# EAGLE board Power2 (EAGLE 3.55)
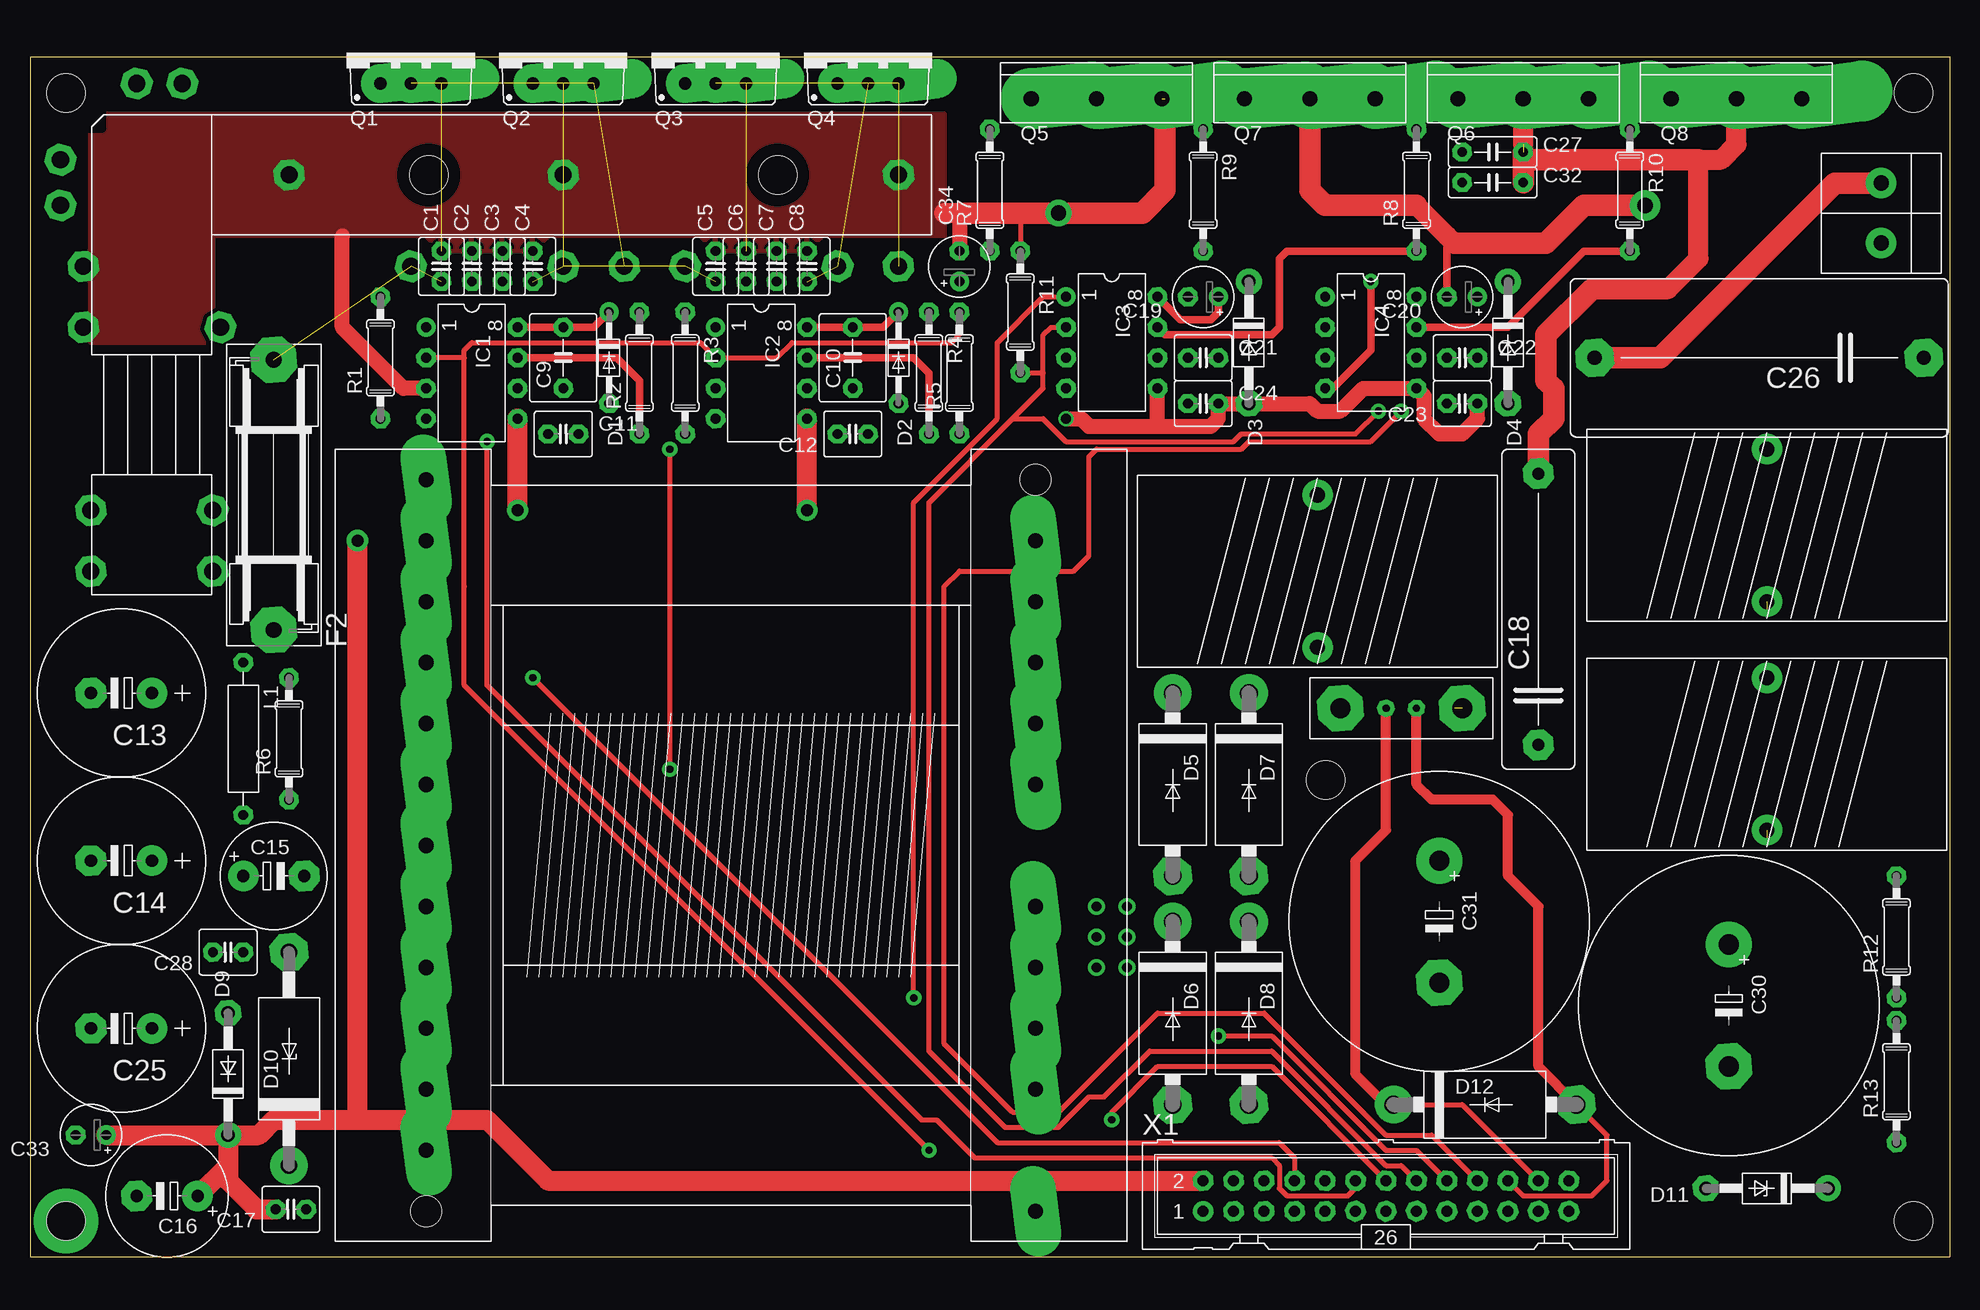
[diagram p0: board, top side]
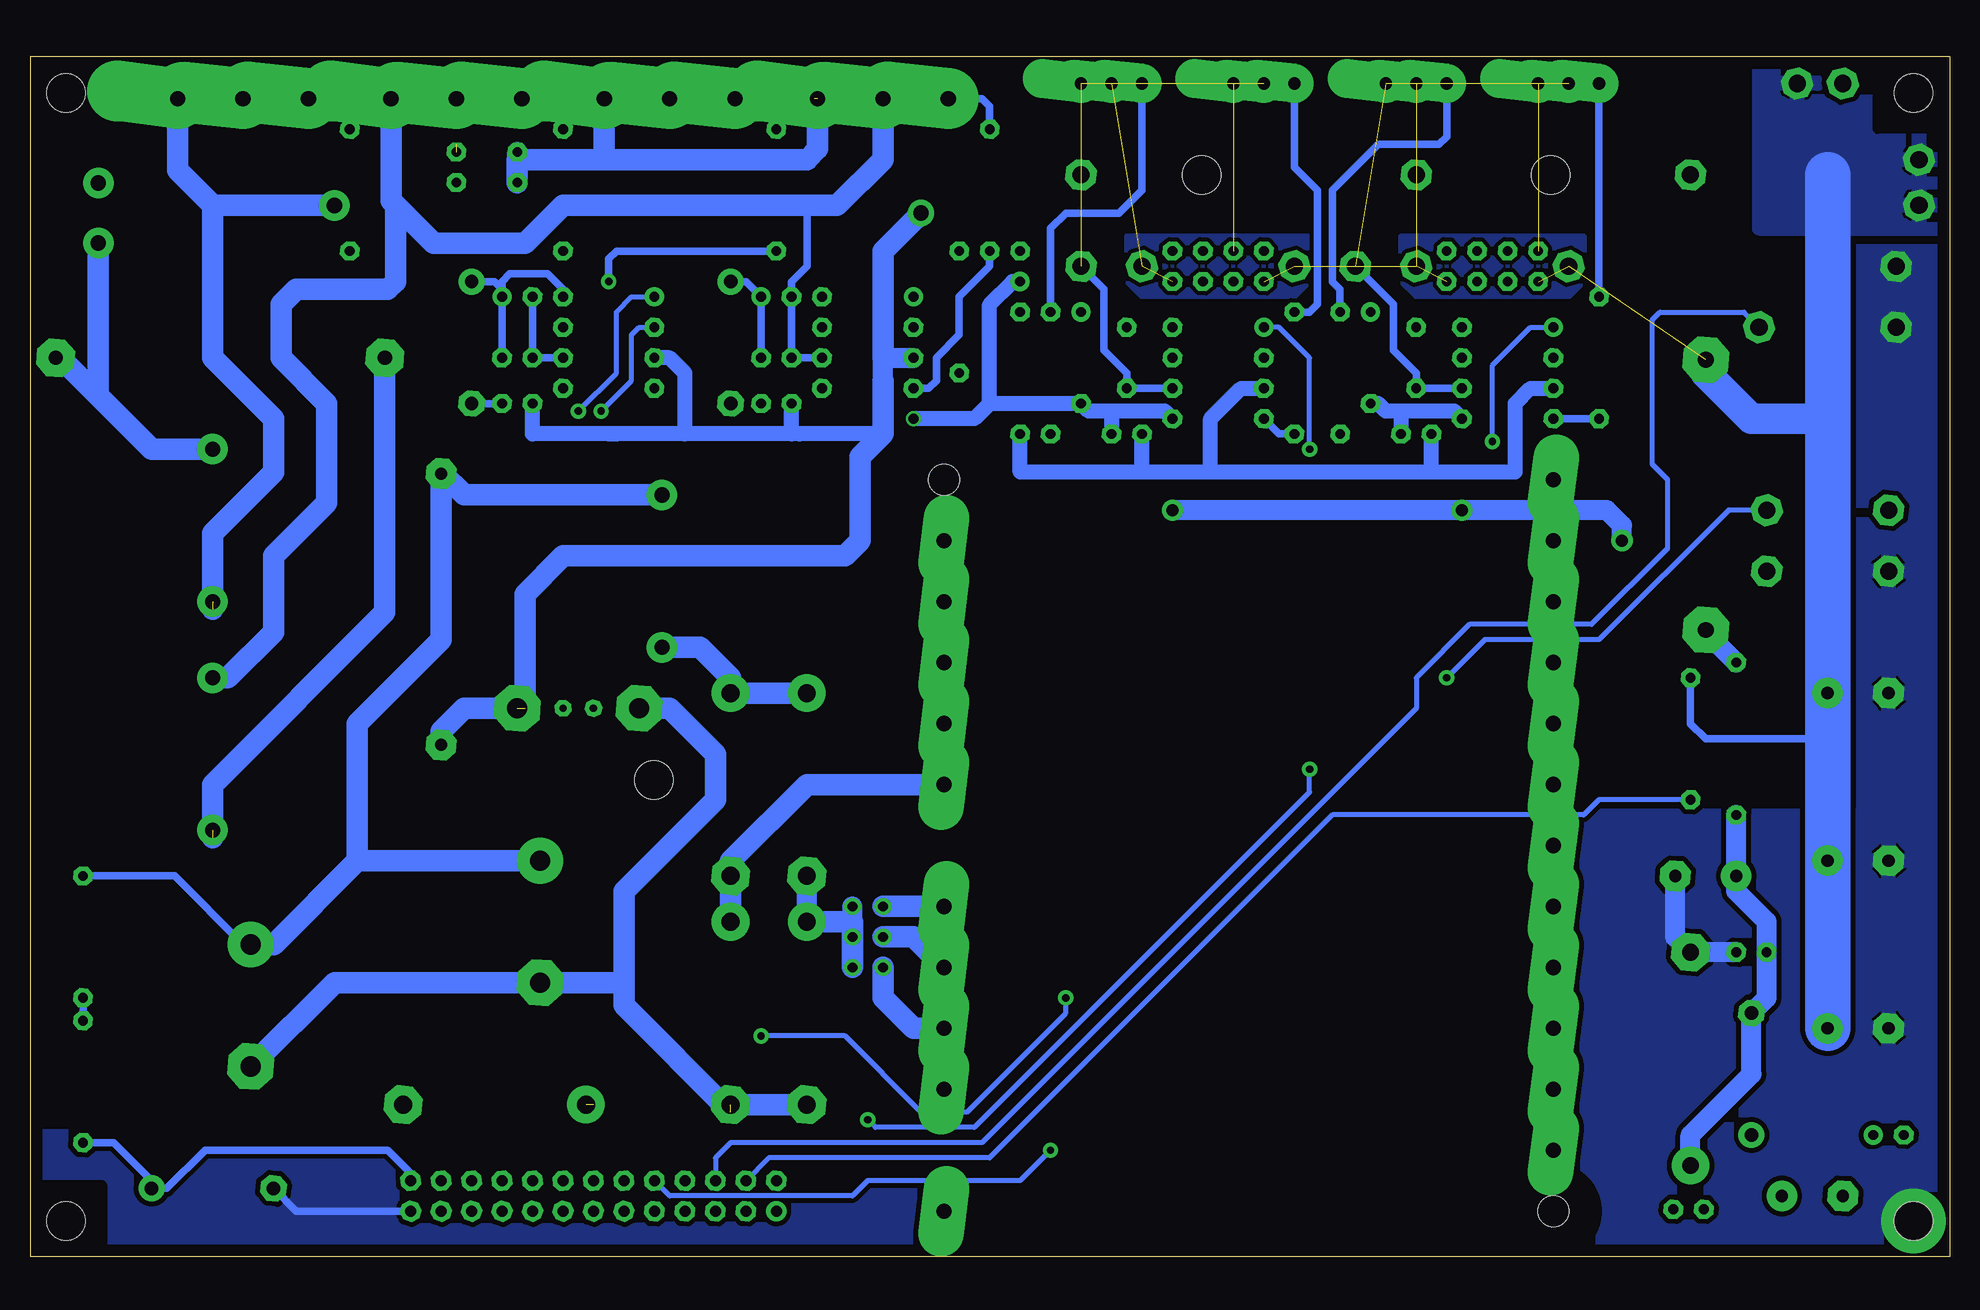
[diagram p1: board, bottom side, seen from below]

Size 160 x 100 mm. Coordinates in mm from the lower left corner, seen from the top.
Outline: 0,100 0,0 160,0 160,100 0,100
Copper layers used: Top, Bottom
Holes 3.2 mm at 3,97 3,3 157,3 157,97 108,39.73
tRestrict: area 0,94 to 6,100; area 0,0 to 6,6; area 154,94 to 160,100; area 154,0 to 160,6; area 31.8,2.5 to 34.3,5.1; area 82.5,63.5 to 85.1,66; area 105.8,37.5 to 110.2,42
bRestrict: area 0,94 to 6,100; area 154,0 to 160,6; area 154,94 to 160,100; area 30.5,1.3 to 35.6,6.3; area 81.3,62.2 to 86.4,67.3; area 105.8,37.5 to 110.2,42

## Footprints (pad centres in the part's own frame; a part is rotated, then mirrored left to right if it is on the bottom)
,5-4 = drill 0.813 pad 1.6 octagon:  -1.27,0;  1.27,0
B5,5 = drill 0.813 pad 1.6 octagon:  -2.54,0;  2.54,0
-13 = drill 1.016 pad 2.54 round:  -2.54,0 | drill 1.016 pad 2.54 octagon:  2.54,0
-8,5 = drill 1.016 pad 2.54 round:  -2.54,0 | drill 1.016 pad 2.54 octagon:  2.54,0
-10,5 = drill 1.016 pad 2.54 round:  -2.54,0 | drill 1.016 pad 2.54 octagon:  2.54,0
2,5B6 = drill 1.016 pad 2.54 octagon:  -11.303,0;  11.303,0
,5-5 = drill 0.813 pad 1.6 octagon:  1.27,0 | drill 0.813 pad 1.6 round:  -1.27,0
7,5B13 = drill 1.194 pad 3.15 octagon:  -13.716,0;  13.716,0
B2,5 = drill 0.813 pad 1.6 octagon:  -2.54,0;  2.54,0
0 = drill 1.676 pad 3.81 round:  -5.08,0 | drill 1.676 pad 3.81 octagon:  5.08,0
34-7 = drill 0.813 pad 1.6 round:  -3.81,0 | drill 0.813 pad 1.6 octagon:  3.81,0
41-10 = drill 1.118 pad 2.159 octagon:  5.08,0 | drill 1.118 pad 2.159 round:  -5.08,0
201-15 = drill 1.499 pad 3.15 round:  -7.62,0 | drill 1.499 pad 3.15 octagon:  7.62,0
429-17 = drill 1.397 pad 3.15 round:  -8.89,0 | drill 1.397 pad 3.15 octagon:  8.89,0
41Z10 = drill 1.118 pad 2.159 round:  -5.08,0 | drill 1.118 pad 2.159 octagon:  5.08,0
22,5 = drill 1.321 pad 3.81 octagon:  -11.252,0;  11.252,0
D_HOLE = drill 3.2 pad 5.4 round:  0,0
L08 = drill 0.813 pad 1.6 round:  -3.81,-3.81 | drill 0.813 pad 1.6 octagon:  -1.27,-3.81;  1.27,-3.81;  3.81,-3.81;  3.81,3.81;  1.27,3.81;  -1.27,3.81;  -3.81,3.81
SW = drill 0.813 pad 1.397 round: 1 1.27,2.54; 2 1.27,0; 3 1.27,-2.54;  -1.27,2.54;  -1.27,0;  -1.27,-2.54
12,5 = drill 0.813 pad 1.6 octagon:  -6.35,0;  6.35,0
OSSEL1 = drill 1.27 pad 2.54 round:  -6.35,0;  6.35,0
220BS = drill 1.016 pad 3.251 offset:  -2.54,-2.54;  0,-2.54;  2.54,-2.54
247 = drill 1.27 pad 5.08 offset:  0,0;  -5.45,0;  5.45,0
07/10 = drill 0.813 pad 1.6 octagon:  -5.08,0;  5.08,0
AFO = drill 1.27 pad 3.81 long: 0 -25.4,-15.24; 0 25.4,0; 1 25.4,-5.08; 1 -25.4,-20.32; 2 -25.4,-25.4; 2 25.4,-10.16; 3 25.4,-15.24; 4 25.4,-20.32; 5 25.4,25.4; 5 25.4,-25.4; 6 25.4,20.32; 6 25.4,-30.48; 7 25.4,15.24; 8 25.4,10.16; 9 25.4,5.08;  -25.4,5.08;  -25.4,20.32;  -25.4,15.24;  -25.4,10.16;  -25.4,-5.08;  -25.4,-10.16;  -25.4,30.48 | hole 2.54: -25.4,-30.48; 25.4,30.48
DG50A = drill 1.422 pad 2.54 octagon: 1 21.59,-7.62; 1 11.43,0; 2 34.29,-7.62; 2 34.29,0; 3 44.45,-7.62; 3 62.23,0; 4 -5.715,-7.62; 4 5.08,-33.02; 4 57.15,-7.62; 5 -5.715,-12.7; 5 -1.27,7.62; 5 -5.08,-33.02; 6 2.54,7.62; 6 -5.08,-27.94; 7 -7.62,-2.54; 8 -7.62,1.27;  39.37,-7.62;  62.23,-7.62;  5.08,-27.94;  5.715,-12.7 | hole 3.2: 23.08,0; 52.16,0
UNT1 = drill 1.676 pad 3.81 octagon:  -12.7,5.08;  -2.54,5.08 | drill 0.61 pad 1.397 octagon:  -8.89,5.08;  -6.35,5.08
26 = drill 0.914 pad 1.676 round:  -15.24,-1.27 | drill 0.914 pad 1.676 octagon:  -15.24,1.27;  -12.7,-1.27;  -12.7,1.27;  -10.16,-1.27;  -10.16,1.27;  -7.62,-1.27;  -7.62,1.27;  -5.08,-1.27;  -5.08,1.27;  -2.54,-1.27;  -2.54,1.27;  0,-1.27;  0,1.27;  2.54,-1.27;  2.54,1.27;  5.08,-1.27;  5.08,1.27;  7.62,-1.27;  7.62,1.27;  10.16,-1.27;  10.16,1.27;  12.7,-1.27;  12.7,1.27;  15.24,-1.27;  15.24,1.27
2X5 = drill 1.27 pad 2.54 round:  0,2.5;  0,-2.5

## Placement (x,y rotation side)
C1  100n  [,5-4]  34.29,82.55 90 top
C2  100n  [,5-4]  36.83,82.55 90 top
C3  100n  [,5-4]  39.37,82.55 90 top
C4  100n  [,5-4]  41.91,82.55 90 top
C5  100n  [,5-4]  57.15,82.55 90 top
C6  100n  [,5-4]  59.69,82.55 90 top
C7  100n  [,5-4]  62.23,82.55 90 top
C8  100n  [,5-4]  64.77,82.55 90 top
C9  1æ  [B5,5]  44.45,74.93 90 top
C10  1æ  [B5,5]  68.58,74.93 90 top
C11  100n  [,5-4]  44.45,68.58 0 top
C12  100n  [,5-4]  68.58,68.58 180 top
C13  1000æ  [-13]  7.62,46.99 180 top
C14  1000æ  [-13]  7.62,33.02 180 top
C15  220æ  [-8,5]  20.32,31.75 0 top
C16  100æ  [-10,5]  11.43,5.08 180 top
C17  100n  [,5-4]  21.75,3.97 180 top
C18  220n 400V  [2,5B6]  125.73,53.98 90 top
C19  4,7æ  [,5-5]  97.79,80.01 180 top
C20  4,7æ  [,5-5]  119.38,80.01 180 top
C21  100n  [,5-4]  97.79,74.93 0 top
C22  100n  [,5-4]  119.38,74.93 0 top
C23  C2,5  [,5-4]  119.38,71.12 180 top
C24  C2,5  [,5-4]  97.79,71.12 0 top
C25  1000æ  [-13]  7.62,19.05 180 top
C26  1æ 400V  [7,5B13]  144.15,74.93 180 top
C27  10n 400V  [B2,5]  121.92,92.08 0 top
C28  100n  [,5-4]  16.51,25.4 180 top
C30  220æ 400V  [0]  141.6,20.95 270 top
C31  220æ 400V  [0]  117.47,27.94 270 top
C32  10n 400V  [B2,5]  121.92,89.53 0 top
C33  10æ  [,5-5]  5.08,10.16 180 top
C34  10æ  [,5-5]  77.47,82.55 90 top
D1  BAT85  [34-7]  48.26,74.93 270 top
D2  BAT85  [34-7]  72.39,74.93 270 top
D3  UF4003  [41-10]  101.6,76.2 270 top
D4  UF4003  [41-10]  123.19,76.2 270 top
D5  UF5400  [201-15]  95.25,39.37 270 top
D6  UF5400  [201-15]  95.25,20.32 270 top
D7  UF5400  [201-15]  101.6,39.37 270 top
D8  UF5400  [201-15]  101.6,20.32 270 top
D9  SB120  [41-10]  16.51,15.24 90 top
D10  15KE22A  [429-17]  21.59,16.51 90 top
D11  6,1V  [41Z10]  144.78,5.71 180 top
D12  1N5408  [201-15]  121.28,12.7 0 top
F2  315mA  [22,5]  20.32,63.5 90 top
GND  GND_HOLE  [D_HOLE]  3,3 0 top
IC1  IR2184  [L08]  36.83,73.66 270 top
IC2  IR2184  [L08]  60.96,73.66 270 top
IC3  IR2184  [L08]  90.17,76.2 270 top
IC4  IR2184  [L08]  111.76,76.2 270 top
JMP1  TRSW  [SW]  90.17,26.67 180 top
L1  47æH  [12,5]  17.78,43.18 270 top
L2  330æH  [OSSEL1]  107.31,57.15 270 top
L3  330æH  [OSSEL1]  144.78,41.91 90 top
L4  330æH  [OSSEL1]  144.78,60.96 90 top
Q1  IRF1404  [220BS]  31.75,100.33 0 top
Q2  IRF1404  [220BS]  44.45,100.33 0 top
Q3  IRF1404  [220BS]  57.15,100.33 0 top
Q4  IRF1404  [220BS]  69.85,100.33 0 top
Q5  IRFP450  [247]  88.9,96.52 0 top
Q6  IRFP450  [247]  124.46,96.52 0 top
Q7  IRFP450  [247]  106.68,96.52 0 top
Q8  IRFP450  [247]  142.24,96.52 0 top
R1  4R7  [07/10]  29.21,74.93 90 top
R2  4R7  [07/10]  50.8,73.66 90 top
R3  4R7  [07/10]  54.61,73.66 270 top
R4  4R7  [07/10]  74.93,73.66 270 top
R5  10k  [07/10]  77.47,73.66 90 top
R6  22k  [07/10]  21.59,43.18 90 top
R7  10R  [07/10]  80.01,88.9 90 top
R8  10R  [07/10]  115.57,88.9 90 top
R9  10R  [07/10]  97.79,88.9 270 top
R10  10R  [07/10]  133.35,88.9 270 top
R11  10k  [07/10]  82.55,78.74 270 top
R12  330k  [07/10]  155.57,26.67 90 top
R13  330k  [07/10]  155.57,14.61 90 top
TR1  TRAFO  [AFO]  58.42,34.29 180 top
U$1  BRDG50A  [DG50A]  10.16,90.17 0 top
U$2  SHUNT1  [UNT1]  121.92,40.64 0 top
X1  ML26  [26]  113.03,5.08 0 top
X2  KL2X5  [2X5]  154.31,87 0 top

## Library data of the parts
C1-C12 C17 C18 C21-C24 C26-C28 C32 = CAP
C13-C16 C19 C20 C25 C33 C34 = POLCAP
C30 C31 GND IC1-IC4 JMP1 L2-L4 Q5-Q8 TR1 U$1 U$2 X2 = Andreas2
D1-D12 = DIODE
F2 = FUSE
L1 = DISCRETE
Q1-Q4 = TRANS-PW
R1-R13 = R
X1 = CON-ML

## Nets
+12V: C1. C2. C3. C4. C5. C6. C7. C8. C13. C14. C25. F2. Q2. Q4. R6. U$1.1 U$1.2 U$1.3 U$1.4 U$1.5 U$1.6 U$1.7 U$1.8
BRA_1: IC1. X1.
BRA_2: IC2. X1.
BRA_EN: IC1. IC2. R5. X1.
BRB_1: IC3. X1.
BRB_2: IC4. X1.
BRB_EN: IC3. IC4. R11. X1.
GND: C1. C2. C3. C4. C5. C6. C7. C8. C11. C12. C13. C14. C15. C16. C17. C18. C23. C24. C25. C27. C28. C32. C33. C34. D10. D11. GND. IC1. IC2. IC3. IC4. Q1. Q3. Q5. Q7. R5. R11. U$1.1 U$1.2 U$1.3 U$1.4 U$1.5 U$2. X1.
IIN+: U$1. X1.
IIN-: U$1. X1.
IOUT+: D12. U$2. X1.
IOUT-: D12. U$2. X1.
N$1: C9. IC1. Q1. Q2. U$1.
N$2: IC1. R2.
N$3: IC1. R1.
N$4: C26. L3. X2.
N$5: F2. L1.
N$6: Q2. R2.
N$7: Q1. R1.
N$8: Q3. R3.
N$9: Q4. R4.
N$11: C10. IC2. Q3. Q4. U$1.
N$12: C10. D2. IC2.
N$13: C9. D1. IC1.
N$14: C30. C31. D6. D8. U$2.
N$15: D7. D8. TR1.
N$17: D5. D6. JMP1.
N$18: JMP1.1 TR1.
N$19: R6. X1.
N$20: JMP1.2 TR1.
N$21: D5. D7. L2.
N$22: IC2. R4.
N$23: C19. C21. IC3. L3. Q5. Q6.
N$24: JMP1.3 TR1.
N$26: C20. C22. IC4. L4. Q7. Q8.
N$27: C26. L4. X2.
N$29: IC2. R3.
N$30: Q6. R8.
N$31: Q5. R7.
N$32: Q8. R10.
N$33: Q7. R9.
N$34: IC3. R7.
N$35: IC4. R9.
N$36: IC3. R8.
N$37: IC4. R10.
N$38: C19. C21. D3. IC3.
N$41: R12. R13.
N$42: C15. C28. D9. D10. L1.
N$46: C20. C22. D4. IC4.
UZK: D11. R13. X1.
VCC: C11. C12. C16. C17. C23. C24. C33. C34. D1. D2. D3. D4. D9. IC1. IC2. IC3. IC4. X1.
ZK+: C18. C27. C30. C31. C32. L2. Q6. Q8. R12.

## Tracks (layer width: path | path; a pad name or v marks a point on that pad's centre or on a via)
+12V  (8 unrouted)
  Bottom 0.61: R6. 21.59,44.45 20.32,43.18 10.16,43.18
  Bottom 2.54: F2. 20.32,73.66 16.51,69.85 10.16,69.85
  Bottom 3.81: 10.16,90.17 10.16,69.85 10.16,46.99 10.16,43.18 10.16,33.02 10.16,19.05
  pour Bottom (isolate 0.356): 30.48,85.09 30.48,81.28 31.75,80.01 43.18,80.01 44.45,80.01 45.72,81.28 45.72,85.09
  pour Bottom (isolate 0.356): 53.34,85.09 53.34,81.28 54.61,80.01 66.04,80.01 67.31,80.01 68.58,81.28 68.58,85.09
  pour Bottom (isolate 0.406): 0,100.33 15.88,100.33 15.88,85.72 0,85.72
BRA_1  (via drill 0.61 pad 1.27)
  Top 0.406: v38.1,67.94 38.1,47.62 74.3,11.43 75.56,11.43 78.74,8.26 103.5,8.26 104.14,7.62 104.14,5.71 104.78,5.08 109.86,5.08 110.49,5.71 110.49,6.35
  Bottom 0.406: 33.02,77.47 34.92,77.47 38.1,74.3 v38.1,67.94
BRA_2  (via drill 0.61 pad 1.27)
  Top 0.406: 113.03,6.35 103.5,15.88 93.98,15.88 90.17,12.06 v90.17,11.43 | v53.34,40.64 v53.34,67.31
  Bottom 0.406: 57.15,77.47 55.88,77.47 53.34,74.93 v53.34,67.31 | v90.17,11.43 89.53,10.79 81.28,10.79 53.34,38.73 v53.34,40.64
BRA_EN  (via drill 0.61 pad 1.27)
  Top 0.406: R5. 77.47,76.83 76.83,76.2 63.5,76.2 62.23,74.93 57.15,74.93 55.88,76.2 36.83,76.2 36.2,75.56 36.2,74.93 | 36.2,74.93 36.2,55.88 36.2,47.62 v74.93,8.89 | 36.2,74.93 33.02,74.93
  Bottom 0.406: 107.95,6.35 106.68,5.08 91.44,5.08 90.17,6.35 77.47,6.35 v74.93,8.89
BRB_1  (via drill 0.61 pad 1.27)
  Top 0.406: 86.36,80.01 84.45,80.01 80.64,76.2 80.64,69.85 73.66,62.87 v73.66,21.59 | 118.11,6.35 115.57,8.89 113.03,8.89 103.5,18.41 v99.06,18.41
  Bottom 0.406: v99.06,18.41 92.08,18.41 85.72,12.06 81.92,12.06 73.66,20.32 v73.66,21.59
BRB_2  (via drill 0.61 pad 1.27)
  Top 0.406: v114.3,70.48 111.76,67.94 101.6,67.94 100.97,67.31 88.9,67.31 88.27,66.67 88.27,58.42 87,57.15 77.47,57.15 76.2,55.88 76.2,17.78 81.92,12.06 85.72,12.06 93.98,20.32 102.87,20.32 113.03,10.16 116.84,10.16 120.65,6.35
  Bottom 0.406: 107.95,80.01 109.86,80.01 111.12,78.74 111.12,73.66 v114.3,70.48
BRB_EN  (via drill 0.61 pad 1.27)
  Top 0.406: v112.39,70.48 110.49,68.58 100.97,68.58 100.33,67.94 86.36,67.94 84.45,69.85 81.92,69.85 | 86.36,77.47 85.09,77.47 84.45,76.83 84.45,73.66 | 84.45,73.66 84.45,72.39 81.92,69.85 | 81.92,69.85 74.93,62.87 74.93,17.14 81.28,10.79 85.72,10.79 88.27,13.34 89.53,13.34 93.34,17.14 103.5,17.14 113.03,7.62 114.3,7.62 115.57,6.35 | 84.45,73.66 R11.
  Bottom 0.406: 107.95,77.47 109.22,77.47 109.86,76.83 109.86,73.03 v112.39,70.48
GND  (via drill 1.27 pad 2.18)  (4 unrouted)
  Top 0.406: 82.55,87 82.55,83.82
  Top 1.27: 33.02,72.39 31.11,72.39 26.04,77.47 26.04,85.09 | 77.47,87 77.47,83.82
  Top 1.676: 77.47,87 76.2,87 | v85.72,87 86.36,87
  Top 1.778: 77.47,87 82.55,87 86.36,87 92.71,87 94.61,88.9 94.61,96.52
  Bottom 0.61: D11. 137.79,3.81 128.27,3.81
  Bottom 1.27: 33.02,72.39 34.92,72.39 36.2,71.12 36.2,65.41 43.18,65.41 | 43.18,65.41 61.59,65.41 | 61.59,65.41 67.31,65.41 | 67.31,65.41 77.47,65.41 77.47,68.58 | 57.15,72.39 59.05,72.39 61.59,69.85 61.59,65.41 | 67.31,65.41 C12. | 43.18,65.41 43.18,68.58 | C23. 118.11,68.58 111.76,68.58 | 111.76,68.58 111.12,68.58 | 96.52,71.12 96.52,68.58 95.89,68.58 | 88.9,68.58 95.89,68.58 | 95.89,68.58 105.41,68.58 | 105.41,68.58 111.76,68.58 | 107.95,74.93 106.68,74.93 105.41,73.66 105.41,68.58
  Bottom 1.676: C15. 22.86,26.67 D10. 17.78,25.4 | 88.9,73.66 88.9,73.03 88.9,74.93 86.36,74.93 | 119.38,91.44 119.38,92.08
  Bottom 1.778: 88.9,73.03 88.9,68.58 90.81,66.67 90.81,59.69 92.08,58.42 115.57,58.42 118.75,55.24 118.75,45.72 123.83,45.72 125.73,43.81 125.73,42.67 | 119.38,89.53 119.38,91.44 111.76,91.44 | 88.9,74.93 88.9,83.82 v85.72,87 | Q7. 112.13,91.81 111.76,91.44 | 111.76,91.44 95.25,91.44 94.35,92.34 Q5.
  pour Top (isolate 0.356): 6.35,95.25 76.2,95.25 76.2,85.09 66.04,85.09 64.77,83.82 57.15,83.82 55.88,85.09 43.18,85.09 41.91,83.82 34.29,83.82 33.02,85.09 15.24,85.09 15.24,76.2 5.08,76.2 5.08,93.98 5.08,93.98
  pour Bottom (isolate 0.406): 7.62,7.62 7.62,83.82 0,83.82 0,7.62
  pour Bottom (isolate 0.356, no thermals): -1.27,8.89 6.35,8.89 6.35,-1.27 -1.27,-1.27
  pour Bottom (isolate 0.406): 163.83,-1.27 6.35,-1.27 6.35,36.83 73.66,36.83 73.66,10.16 163.83,10.16
IIN+
  Bottom 0.406: U$1. 17.14,78.74 24.13,78.74 24.77,78.11 24.77,66.04 23.5,64.77 23.5,59.05 29.84,52.7 40.01,52.7 44.45,48.26 44.45,45.72 80.64,9.53 101.6,9.53 102.87,8.26 102.87,6.35
IIN-  (via drill 0.61 pad 1.27)
  Top 0.406: 105.41,6.35 105.41,8.26 104.14,9.53 80.64,9.53 v41.91,48.26
  Bottom 0.406: 15.24,62.23 18.41,62.23 29.21,51.44 38.73,51.44 v41.91,48.26
IOUT+
  Top 0.406: 123.19,6.35 124.46,5.08 130.18,5.08 131.44,6.35 131.44,10.16 D12.
  Top 0.813: U$2. 115.57,39.37 116.84,38.1 121.92,38.1 123.19,36.83 123.19,31.75 125.73,29.21 125.73,15.88 D12.
IOUT-  (1 unrouted)
  Top 0.406: 113.67,12.7 119.38,12.7 125.73,6.35
  Top 0.813: 113.03,45.72 113.03,35.56 110.49,33.02 110.49,15.24 113.03,12.7
N$1  (2 unrouted)
  Bottom 0.61: 40.64,72.39 44.45,72.39 44.45,73.66 46.35,75.56 46.35,79.38 49.53,82.55
N$2
  Top 0.61: 40.64,74.93 48.9,74.93 50.8,73.03 50.8,68.58
N$3
  Bottom 0.61: 29.21,69.85 33.02,69.85
N$4  (1 unrouted)
  Top 1.778: C26. 135.89,74.93 150.46,89.5 154.31,89.5
  Bottom 1.778: C26. 130.43,53.72 144.78,39.37 144.78,34.92
N$5
  Bottom 1.676: 20.32,52.25 20.32,52.07 17.78,49.53
N$6
  Bottom 0.61: R2. 50.8,80.64 51.44,81.28 51.44,88.9 47.62,92.71 42.55,92.71 41.91,93.34 41.91,97.79
N$7
  Bottom 0.61: R1. 29.21,97.79
N$8
  Bottom 0.61: 54.61,78.74 53.34,78.74 52.7,79.38 52.7,88.9 54.61,90.81 54.61,97.79
N$9
  Bottom 0.61: 74.93,78.74 74.93,85.72 73.66,87 69.22,87 67.31,88.9 67.31,97.79
N$11  (2 unrouted)
  Bottom 0.61: 64.77,72.39 68.58,72.39 68.58,73.66 70.48,75.56 70.48,80.64 72.39,82.55
N$12
  Top 0.61: 72.39,78.74 71.12,77.47 C10. IC2.
N$13
  Top 0.61: 48.26,78.74 46.99,77.47 C9. IC1.
N$14  (1 unrouted)
  Bottom 1.676: 110.49,23.5 111.12,22.86
  Bottom 1.778: C30. 134.62,22.86 C31. 111.12,22.86 | 101.6,12.06 110.49,20.95 110.49,23.5 110.49,30.48 102.87,38.1 102.87,41.91 106.68,45.72 109.22,45.72 | D6. D8.
N$15
  Bottom 1.778: 101.6,27.94 D7. 101.6,33.02 95.25,39.37 83.82,39.37
N$17
  Bottom 1.676: 91.44,27.94 JMP1. | 95.25,27.94 D5.
  Bottom 1.778: 91.44,24.13 91.44,26.67 91.44,27.94 95.25,27.94
N$18
  Bottom 1.778: JMP1.1 88.9,21.59 86.36,19.05 83.82,19.05
N$19
  Bottom 0.406: 21.59,38.1 29.21,38.1 30.48,36.83 51.44,36.83 80.01,8.26 98.42,8.26 100.33,6.35
N$20
  Bottom 1.778: JMP1.2 86.36,26.67 83.82,24.13
N$21
  Bottom 1.676: 101.6,46.99 101.6,48.26
  Bottom 1.778: 95.25,46.99 101.6,46.99 | 101.6,48.26 104.14,50.8 L2.
N$22
  Top 0.61: 64.77,74.93 73.66,74.93 74.93,73.66 R4.
N$23
  Bottom 0.61: 93.98,74.93 96.52,74.93 96.52,80.01 96.52,81.28 95.25,82.55 95.25,87.63
  Bottom 1.778: 88.9,96.52 88.9,91.44 92.71,87.63 95.25,87.63 115.57,87.63 118.75,84.45 126.36,84.45 129.54,87.63 | 129.54,87.63 129.54,81.28 130.18,80.64 137.79,80.64 139.06,79.38 139.06,74.93 135.25,71.12 135.25,62.87 139.7,58.42 139.7,52.07 143.51,48.26 L3. | Q6. 129.91,88 129.54,87.63
N$24
  Bottom 1.778: 83.82,29.21 JMP1.3
N$26  (via drill 1.27 pad 2.54)  (1 unrouted)
  Top 0.61: 118.11,80.01 118.11,85.09
  Top 1.676: 118.75,84.45 118.11,85.09 115.57,87.63
  Top 1.778: 106.68,96.52 106.68,88.9 107.95,87.63 115.57,87.63 | v134.62,87.63 129.54,87.63 126.36,84.45 118.75,84.45
  Bottom 0.61: 115.57,74.93 118.11,74.93 118.11,80.01
  Bottom 1.778: Q8. 147.69,90.54 144.78,87.63 | v134.62,87.63 144.78,87.63 | 144.78,87.63 144.78,74.93 139.7,69.85 139.7,65.41 144.78,60.33 144.78,53.98
N$27
  Bottom 1.676: 157.48,74.93 157.86,74.93
  Bottom 1.778: L4. 149.86,67.31 154.31,71.75 | 154.31,71.75 157.48,74.93 | 154.31,71.75 X2.
N$29
  Bottom 0.61: 57.15,69.85 55.88,68.58 R3.
N$30
  Bottom 0.61: 119.01,96.52 116.2,96.52 115.57,95.89 R8.
N$31
  Bottom 0.61: 83.45,96.52 80.64,96.52 80.01,95.89 R7.
N$32
  Bottom 0.61: 136.79,96.52 133.99,96.52 133.35,95.89 133.35,93.98
N$33
  Bottom 0.61: 101.23,96.52 98.42,96.52 97.79,95.89 97.79,93.98
N$34
  Bottom 0.61: 80.01,83.82 80.01,82.55 82.55,80.01 82.55,76.83 84.45,74.93 84.45,73.03 85.09,72.39 86.36,72.39
N$35  (via drill 0.61 pad 1.27)
  Top 0.61: v111.76,81.28 111.76,75.56 108.58,72.39 107.95,72.39
  Bottom 0.61: R9. 111.12,83.82 111.76,83.19 v111.76,81.28
N$36
  Top 0.61: 115.57,83.82 104.78,83.82 104.14,83.19 104.14,77.47 103.5,76.83 94.61,76.83 93.98,77.47
N$37
  Top 0.61: 115.57,77.47 123.19,77.47 129.54,83.82 R10.
N$38
  Top 0.61: IC3. 95.89,78.11 98.42,78.11 99.06,78.74 C19.
  Bottom 0.61: C21. C19. 100.33,81.28 D3.
N$41
  Bottom 0.61: R13. 155.57,21.59
N$42
  Bottom 1.676: L1. 17.78,31.75 17.78,30.48 15.24,27.94 C28. 15.24,21.59 16.51,20.32 16.51,15.24 21.59,10.16 21.59,7.62
N$46
  Bottom 0.61: C22. C20. | C20. 120.65,80.64 121.28,81.28 D4. | IC4. 115.57,80.64 116.84,81.92 120.02,81.92 120.65,81.28 C20.
UZK
  Bottom 0.61: 155.57,9.53 153.03,9.53 149.22,5.71 149.86,5.71 148.59,5.71 145.41,8.89 130.18,8.89 128.27,6.99 X1.
VCC  (via drill 0.81 pad 1.27, 1.02 pad 1.78)
  Top 1.27: v86.36,69.85 87.63,69.85 88.27,69.22 93.98,69.22 | 93.98,69.22 98.42,69.22 99.06,69.85 C24. 101.6,71.12 106.68,71.12 107.31,70.48 109.22,70.48 111.12,72.39 115.57,72.39 116.2,71.75 116.2,69.85 117.47,68.58 119.38,68.58 120.65,69.85 120.65,71.12 | 93.98,69.22 93.98,72.39
  Top 1.676: C17. 18.89,3.97 16.51,6.35 16.51,7.62 | D9. 19.05,10.16 20.32,11.43 27.3,11.43 | v64.77,62.23 64.77,69.85 | v40.64,62.23 40.64,69.85 | 97.79,6.35 43.18,6.35 38.1,11.43 27.3,11.43 | C33. D9. | D9. 16.51,7.62 | 16.51,7.62 13.97,5.08 | 27.3,11.43 v27.3,59.69
  Bottom 0.61: 120.65,71.12 123.19,71.12
  Bottom 1.27: 40.64,69.85 41.27,70.48 45.72,70.48 | 67.94,70.48 65.41,70.48 64.77,69.85 | 67.94,70.48 68.58,70.48 | D1. 47.62,71.12 46.99,70.48 45.72,70.48 | 45.72,70.48 C11. | 67.94,70.48 69.85,70.48 | 69.85,70.48 71.75,70.48 D2. 80.01,71.12 | 69.85,70.48 69.85,68.58 | C34. 78.11,81.28 80.01,79.38 80.01,71.12 | v86.36,69.85 81.28,69.85 80.01,71.12
  Bottom 1.676: v27.3,59.69 27.3,60.96 28.57,62.23 v40.64,62.23 v64.77,62.23
ZK+  (1 unrouted)
  Top 1.676: 142.24,96.52 142.24,92.71 140.97,91.44 139.06,91.44 139.06,83.19 136.53,80.64 130.18,80.64 | 124.46,92.71 124.46,96.52
  Top 1.778: 130.18,80.64 126.36,76.83 126.36,73.03 127,72.39 127,69.85 125.73,68.58 C18. | 124.46,91.44 C32. | 139.06,91.44 124.46,91.44 | 124.46,91.44 C27.
  Bottom 0.61: 141.6,26.04 142.24,26.04 147.96,31.75 R12.
  Bottom 1.676: 125.73,65.41 C18.
  Bottom 1.778: 107.31,63.5 123.83,63.5 125.73,65.41 125.73,51.44 132.72,44.45 132.72,33.02 | 141.6,26.04 139.7,26.04 132.72,33.02 | 117.47,33.02 132.72,33.02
